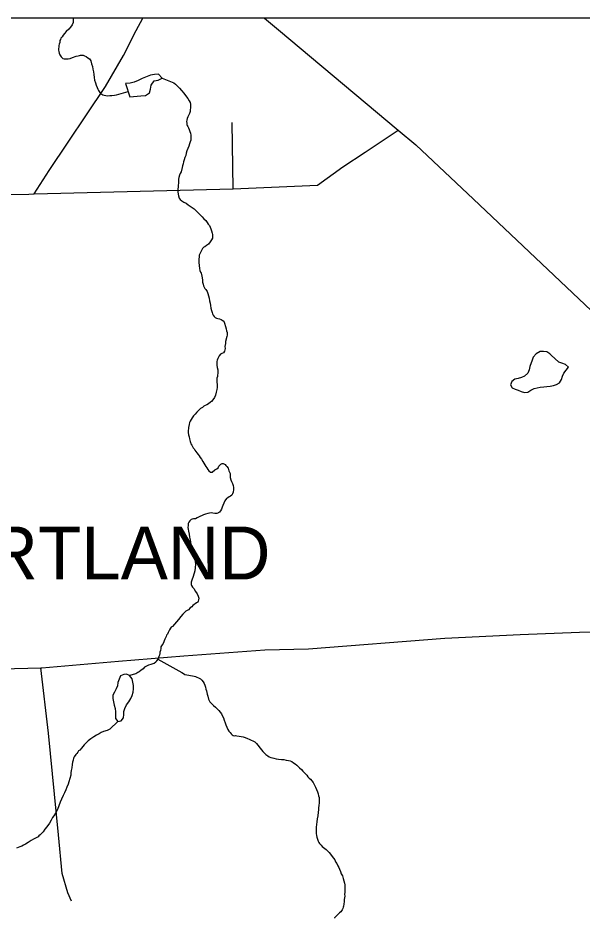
# Model space of a CAD drawing. Extents: x 103424 to 290657, y 38711 to 110967.
# Drawn here: x 109123 to 114482, y 102413 to 110967 of the extents above; entities that cross this region are included whole.
import ezdxf

# ---------------------------------------------------------------- set-up
doc = ezdxf.new("R2010")
doc.units = 0
for name, color, linetype in [('GM_X_City_Street', 7, 'Continuous'), ('GM_X_Corporation', 7, 'Continuous'), ('GM_X_Corporation_Text', 7, 'Continuous'), ('GM_X_County_Road', 7, 'Continuous'), ('GM_X_Minor_Lake', 7, 'Continuous'), ('GM_X_Minor_River', 7, 'Continuous')]:
    doc.layers.add(name, color=color, linetype=linetype)

msp = doc.modelspace()

# ---------------------------------------------------------------- linework, layer by layer
at = {"layer": 'GM_X_City_Street'}
msp.add_line((111163.5, 109345.6), (111153.7, 109973.9), dxfattribs=at)
for points in [[(109276.9, 109296.7), (111163.5, 109345.6), (111963.6, 109379.5), (112203.8, 109555.2), (112414.2, 109693.5), (112729.3, 109903)], [(104950.4, 104745), (108964.7, 104788.8), (109340, 104798.5), (109349.3, 104798.7), (110075.2, 104860), (110696.8, 104911.3), (111463.6, 104967.8), (111877.2, 104979.7), (113170.7, 105079.9), (113887, 105114.4), (114447.9, 105137.7), (115726.2, 105164.6)], [(109629.6, 102581.7), (109595.7, 102662.7), (109542, 102846.8), (109505.3, 103212.7), (109410.6, 104176.7), (109340, 104798.5)]]:
    msp.add_lwpolyline(points, dxfattribs=at)
at = {"layer": 'GM_X_Corporation'}
for points in [[(119699, 110967.2), (103423.7, 110967.2), (103423.7, 96534.8), (105081.7, 96574.5), (115542.1, 96665), (117026.4, 96688.2), (119663.9, 96690), (119706.4, 99064.2), (119709.7, 99445.7), (119720.8, 106006.3), (119719.8, 106322.8), (119716.9, 106542.5)], [(119675.5, 110967.2), (103423.7, 110967.2), (103423.7, 96476), (115542.1, 96665), (117026.4, 96688.2), (119663.9, 96690), (119681.7, 104183.1)], [(119699, 110967.2), (103423.7, 110967.2), (103423.7, 96534.8), (105081.7, 96574.5), (115542.1, 96665), (117026.4, 96688.2), (119663.9, 96690), (119706.4, 99064.2), (119709.7, 99445.7), (119720.8, 106006.3), (119719.8, 106322.8), (119716.9, 106542.5)]]:
    msp.add_lwpolyline(points, close=True, dxfattribs=at)
at = {"layer": 'GM_X_County_Road'}
for points in [[(109224.4, 109296.1), (109276.9, 109296.7), (109417.9, 109520.3), (109953.3, 110318.4), (110122.9, 110611.3), (110242.6, 110848.4), (110304.9, 110967.2)], [(111460.3, 110967.2), (111593.9, 110854.4), (112729.3, 109903), (112896.9, 109761.7), (113441.7, 109247.9), (114736.9, 108024.1), (115658.3, 107154.3), (115863.9, 106947.2), (116037.8, 106787.5), (116320.7, 106518.6)], [(104647.8, 109085.2), (105525.2, 109102.3), (105615.6, 109103.2), (105627.4, 109113.8), (105659.7, 109143.4), (105802.7, 109276.8), (106245.4, 109275.2), (107068.4, 109272.7), (107334.8, 109274.3), (109224.4, 109296.1)]]:
    msp.add_lwpolyline(points, dxfattribs=at)
at = {"layer": 'GM_X_Minor_Lake'}
msp.add_line((110143.6, 110346), (110183.6, 110217.8), dxfattribs=at)
for points in [[(110490.6, 110396.5), (110456.1, 110434.6), (110417.9, 110432.4), (110377.7, 110424.1), (110301.3, 110394.3)], [(110301.3, 110394.3), (110299.4, 110393.4), (110263.3, 110373.1), (110225.2, 110358.7), (110185, 110348.5), (110143.6, 110346)], [(110183.6, 110217.8), (110252.1, 110225.8), (110288.3, 110228), (110330.5, 110230.3), (110368.6, 110256.7), (110380.5, 110293), (110384.3, 110329.4), (110414.3, 110369.8), (110450.4, 110376.1), (110490.6, 110396.5)], [(114076.7, 107800.6), (114038.8, 107780.2), (114010.8, 107747.8), (113998.9, 107719.5), (113979.1, 107659), (113971.3, 107626.7), (113959.4, 107596.4), (113927.3, 107566), (113899.2, 107553.7), (113867.1, 107545.5), (113834.9, 107539.3), (113806.9, 107516.9), (113795, 107484.6), (113809.2, 107456.5), (113837.5, 107442.5), (113867.7, 107432.6), (113896, 107420.6), (113926.2, 107410.7), (113958.4, 107414.9)], [(114180.6, 107764.9), (114167.6, 107778.9), (114139.3, 107796.9), (114107.1, 107800.7), (114076.7, 107800.6)], [(113958.4, 107414.9), (113986.5, 107433.2), (114018.6, 107449.5), (114074.8, 107461.9), (114109, 107466.1), (114139.2, 107468.3), (114171.3, 107470.5), (114203.5, 107478.7), (114231.6, 107486.9), (114259.7, 107505.2), (114279.6, 107535.5), (114287.5, 107565.8), (114299.4, 107594.1), (114321.4, 107622.4), (114345.4, 107650.8), (114315, 107678.8), (114280.8, 107690.8), (114252.5, 107700.7), (114180.6, 107764.9)], [(110127.1, 104735.9), (110094.3, 104721.3), (110080.4, 104689), (110070.5, 104658.7), (110064.7, 104626.4), (110052.7, 104598.1), (110036.8, 104565.8), (110022.9, 104537.5), (110023.1, 104505.2), (110029.3, 104475), (110033.5, 104444.8), (110043.7, 104412.6), (110048, 104380.3), (110046.1, 104348.1), (110046.3, 104315.8)], [(110046.3, 104315.8), (110068.6, 104287.7), (110100.8, 104293.9), (110122.7, 104324.3), (110126.6, 104354.6), (110126.4, 104384.8), (110136.3, 104413.1), (110152.2, 104445.4), (110174.2, 104473.7), (110192.1, 104506.1), (110204, 104534.4), (110213.9, 104566.7), (110217.8, 104597), (110217.6, 104629.2), (110205.1, 104693.7), (110180.8, 104725.8), (110152.6, 104737.7), (110127.1, 104735.9)]]:
    msp.add_lwpolyline(points, dxfattribs=at)
at = {"layer": 'GM_X_Minor_River'}
for points in [[(109645.5, 110967.2), (109644.5, 110924), (109634.7, 110901.6)], [(109634.7, 110901.6), (109618.9, 110881.2), (109603.1, 110862.8), (109579.2, 110838.2), (109563.4, 110819.8), (109549.5, 110805.4), (109539.7, 110789.1), (109529.8, 110776.9), (109523.9, 110764.6), (109520.1, 110752.5), (109518.3, 110736.3), (109512.6, 110720), (109508.7, 110705.8), (109509, 110693.7), (109507.3, 110673.5), (109507.5, 110661.4), (109509.7, 110649.3), (109512, 110633.1), (109520.3, 110617.1), (109532.7, 110597.1), (109549.1, 110583.2), (109561.3, 110579.3), (109577.4, 110579.6), (109597.6, 110579.9), (109617.7, 110584.2), (109639.8, 110592.6), (109673.9, 110605.2), (109692, 110609.5), (109706.1, 110611.8), (109716.2, 110613.9), (109726.2, 110614.1), (109740.4, 110614.3), (109754.6, 110608.4), (109768.9, 110600.6), (109785.2, 110590.7), (109799.5, 110578.8), (109811.9, 110560.8), (109820.5, 110532.6), (109829, 110506.5), (109833.4, 110480.3), (109837.9, 110456.1), (109840.3, 110429.9), (109844.8, 110401.7), (109849.2, 110377.5), (109857.8, 110351.3), (109864.2, 110329.2), (109872.6, 110309.1), (109878.9, 110293), (109887.2, 110279), (109905.8, 110251), (109916.1, 110243.1), (109928.3, 110237.2), (109940.4, 110233.3), (109956.6, 110231.6), (109974.8, 110227.8), (109993, 110230.1), (110013.1, 110232.4), (110037.3, 110234.8), (110055.4, 110237.1), (110166.6, 110269.4)], [(110490.6, 110396.5), (110600.6, 110352.1), (110617, 110338.2), (110635.5, 110320.3), (110654, 110300.4), (110674.5, 110278.5), (110695.1, 110254.5), (110711.6, 110230.5), (110734.3, 110202.6), (110746.7, 110182.5), (110755.1, 110166.5), (110757.4, 110148.4), (110759.7, 110132.2), (110757.9, 110114), (110756.2, 110095.8), (110754.5, 110079.6), (110748.7, 110061.4), (110742.9, 110049.1), (110733.1, 110028.8), (110727.3, 110014.6), (110723.5, 109998.3), (110721.7, 109984.2), (110724, 109968), (110724.2, 109955.9), (110728.4, 109945.9), (110732.6, 109935.8), (110740.9, 109923.9), (110747.2, 109907.8), (110753.6, 109889.7), (110757.9, 109873.6), (110762.2, 109855.5), (110762.4, 109843.4), (110762.6, 109831.2), (110762.7, 109821.1), (110761, 109807), (110755.2, 109790.7), (110749.4, 109772.4), (110741.7, 109750.1), (110732, 109729.8), (110724.3, 109705.4), (110718.6, 109685.1), (110712.9, 109660.8), (110705.1, 109642.5), (110699.4, 109622.2), (110693.7, 109601.9), (110689.9, 109583.7), (110684.2, 109565.4), (110680.4, 109549.2), (110669, 109506.6), (110661.2, 109490.3), (110653.3, 109476.1), (110647.7, 109453.8), (110645.9, 109437.6), (110644.2, 109421.4), (110644.4, 109407.2), (110644.6, 109395.1), (110642.8, 109383), (110640.9, 109370.8), (110641.1, 109360.7), (110639.3, 109346.5), (110637.6, 109330.4), (110637.8, 109318.2), (110640.2, 109296), (110644.5, 109277.9), (110650.9, 109257.8), (110661.2, 109243.8), (110675.5, 109231.9), (110693.9, 109220.1), (110716.3, 109208.3), (110736.7, 109194.4), (110755.1, 109180.6), (110775.5, 109168.7), (110791.9, 109154.8), (110808.3, 109138.9), (110830.8, 109117), (110851.3, 109099.1), (110869.8, 109081.2), (110886.3, 109061.2), (110902.7, 109043.3), (110917.1, 109027.4), (110927.4, 109011.3), (110937.8, 108997.3), (110946.1, 108981.3), (110952.4, 108965.2), (110958.8, 108947.1), (110965.2, 108925), (110967.5, 108910.9), (110967.6, 108898.8), (110967.8, 108888.7), (110966, 108878.6), (110958.2, 108862.3), (110946.4, 108841.9), (110928.5, 108821.4), (110910.6, 108807), (110894.7, 108794.7), (110884.6, 108790.5), (110872.7, 108778.2)], [(110872.7, 108778.2), (110847.3, 108729.3), (110841.4, 108717.1), (110839.7, 108698.9), (110838.1, 108676.7), (110838.6, 108646.4), (110841.1, 108616.1), (110845.6, 108587.9), (110847.9, 108569.7), (110852.2, 108553.6), (110858.4, 108543.6), (110862.6, 108531.6), (110864.9, 108517.5), (110869.2, 108499.3), (110871.6, 108479.2), (110873.9, 108459), (110878.3, 108440.9), (110882.6, 108424.8), (110888.8, 108410.7), (110895.1, 108398.7), (110903.3, 108388.7), (110915.7, 108370.7), (110922.1, 108352.6), (110930.5, 108330.5), (110935, 108306.3), (110939.4, 108282.2), (110943.8, 108260), (110948.2, 108237.8), (110952.7, 108213.6), (110957, 108191.5), (110963.4, 108171.4), (110967.7, 108157.3), (110974, 108145.3), (110982.2, 108133.3), (110992.5, 108123.3), (111004.7, 108117.4), (111018.9, 108113.6), (111035.1, 108109.8), (111049.3, 108103.9), (111059.5, 108100.1), (111073.8, 108088.1), (111080.2, 108070), (111090.8, 108037.9), (111097.2, 108017.8), (111101.5, 107997.6), (111105.8, 107981.5), (111106.1, 107967.4), (111106.3, 107955.3), (111104.5, 107943.1), (111091.1, 107896.4), (111089.4, 107876.2), (111085.8, 107847.9), (111086.1, 107829.7), (111084.3, 107817.5), (111082.5, 107805.4), (111070.7, 107787), (111054.6, 107780.8), (111042.6, 107776.5), (111030.7, 107760.2), (111024.9, 107748), (111019.1, 107733.8), (111011.3, 107717.5), (111009.4, 107707.3), (111009.6, 107697.3), (111009.7, 107687.2), (111010, 107671), (111012.4, 107648.8), (111016.8, 107626.6), (111017.1, 107604.4), (111017.4, 107592.3), (111015.6, 107578.1), (111013.8, 107564), (111010, 107547.7), (111008.2, 107535.6), (111008.4, 107521.5), (111008.6, 107507.3), (111010.9, 107491.2), (111011.2, 107475), (111011.5, 107458.9), (111007.7, 107440.6), (111002.1, 107414.3), (110994.5, 107387.9), (110984.8, 107363.5), (110971, 107341.1), (110957.1, 107326.7), (110947.1, 107318.5), (110929.2, 107304.1), (110913.2, 107295.8), (110899.2, 107289.5), (110885.2, 107281.2), (110871.3, 107268.9), (110853.3, 107258.5), (110817.5, 107225.7), (110803.6, 107207.3), (110787.8, 107188.9), (110773.9, 107172.5), (110764.1, 107156.2), (110756.3, 107140), (110750.5, 107125.7), (110746.7, 107107.5), (110741.1, 107081.1)], [(110741.1, 107081.1), (110739.2, 107071), (110737.6, 107050.8), (110737.9, 107030.6), (110740.2, 107010.4), (110744.6, 106990.3), (110748.9, 106972.1), (110751.2, 106958), (110755.4, 106948), (110757.6, 106937.9), (110761.8, 106925.9), (110770.1, 106911.8), (110776.4, 106899.8), (110784.6, 106887.8), (110792.9, 106877.8), (110801.2, 106865.8), (110809.5, 106851.8), (110817.8, 106837.8), (110830.1, 106823.8), (110840.4, 106809.8), (110850.8, 106795.8), (110863.1, 106779.9), (110875.6, 106757.8), (110886, 106739.8), (110894.3, 106725.8), (110902.6, 106709.7), (110915, 106695.8), (110923.3, 106681.7), (110933.6, 106667.7), (110947.9, 106655.8), (110964.1, 106654), (110990, 106676.6), (111008, 106687), (111019.9, 106697.3), (111027.8, 106711.6), (111035.7, 106721.8), (111047.6, 106732), (111059.6, 106738.3), (111069.7, 106738.4), (111086, 106728.6), (111094.3, 106718.6), (111102.5, 106708.6), (111116.9, 106692.6), (111123.4, 106668.5), (111133.8, 106644.4), (111136.2, 106626.3), (111136.4, 106614.1), (111136.5, 106604), (111140.9, 106583.9), (111147.2, 106567.8), (111155.6, 106547.7), (111162, 106527.6), (111166.3, 106509.5), (111166.6, 106491.3), (111163, 106465), (111157.2, 106448.8), (111149.3, 106438.5), (111137.4, 106426.2), (111125.4, 106420), (111111.4, 106411.7), (111099.4, 106405.5), (111083.6, 106383), (111075.9, 106362.7), (111066.2, 106338.3), (111058.4, 106322), (111052.6, 106303.8), (111044.8, 106287.5), (111034.9, 106277.3), (111022.9, 106269), (111008.9, 106262.7), (110988.7, 106262.4), (110970.5, 106266.2), (110954.3, 106268), (110938.2, 106265.7), (110922.1, 106263.5), (110900, 106257.1), (110881.9, 106250.8), (110833.8, 106227.8), (110821.8, 106221.6), (110805.8, 106213.3), (110787.7, 106211), (110775.6, 106210.8), (110763.5, 106206.6), (110751.6, 106192.3), (110741.7, 106182.1), (110737.9, 106167.8), (110736.2, 106147.6), (110734.5, 106129.4), (110736.8, 106113.3), (110739.1, 106095.1), (110745.6, 106066.9), (110750.1, 106038.7), (110754.6, 106014.5), (110759, 105990.4), (110761.4, 105970.2), (110761.6, 105954), (110761.8, 105943.9), (110764, 105933.9), (110768.2, 105919.8), (110778.7, 105895.7), (110789.2, 105869.6)], [(110789.2, 105869.6), (110797.8, 105841.4), (110802.2, 105815.2), (110804.9, 105778.9), (110799.8, 105718.2), (110784.6, 105663.4), (110771, 105628.9), (110765.2, 105612.6), (110763.5, 105590.4), (110767.8, 105578.3), (110776.1, 105564.3), (110790.4, 105550.4), (110807.1, 105522.3), (110821.5, 105500.3), (110832, 105478.2), (110836.4, 105458.1), (110834.6, 105441.9), (110830.7, 105431.7), (110828.9, 105421.6), (110816.9, 105413.4), (110781, 105390.6), (110771.1, 105378.3), (110755.1, 105368), (110739.3, 105347.6), (110715.3, 105335.1), (110699.3, 105320.7), (110685.4, 105306.4), (110667.6, 105285.9), (110645.9, 105257.3), (110608.3, 105212.3), (110586.4, 105191.8), (110574.4, 105185.5), (110570.5, 105175.4), (110560.7, 105159.1), (110552.8, 105146.8), (110547, 105132.6), (110539.1, 105118.3), (110531.2, 105108.1), (110527.4, 105095.9), (110521.5, 105083.7), (110515.7, 105071.5), (110500.2, 105028.9), (110488.3, 105016.6), (110478.6, 104996.2), (110476.8, 104980), (110473, 104963.8), (110469.3, 104947.6), (110467.5, 104933.4), (110463.7, 104919.2), (110457.9, 104905), (110454, 104894.8), (110448.2, 104878.6), (110436.3, 104864.3), (110428.5, 104852), (110412.5, 104839.7), (110400.5, 104835.5), (110382.4, 104829.1), (110360.3, 104822.8), (110340.2, 104814.4), (110322.2, 104804), (110308.4, 104789.7), (110286.5, 104771.2), (110270.5, 104758.8), (110258.5, 104754.6), (110240.5, 104742.2), (110238.5, 104740.2), (110180.8, 104725.8)], [(110448.2, 104878.6), (110676.4, 104752.6), (110690.7, 104742.7), (110704.9, 104734.9), (110723.1, 104731.1), (110777.8, 104721.8), (110792, 104717.9), (110806.2, 104716.1), (110818.4, 104710.2), (110834.6, 104702.4), (110853, 104692.6), (110865.3, 104680.6), (110877.7, 104664.6), (110888, 104648.6), (110894.3, 104632.6), (110900.7, 104614.5), (110905, 104596.3), (110909.4, 104578.2), (110913.7, 104562.1), (110917.9, 104548), (110922.3, 104529.9), (110930.8, 104501.8), (110943.3, 104475.7), (110959.8, 104455.7), (110976.2, 104441.8), (110994.6, 104425.9), (111011, 104410), (111027.4, 104394.1), (111039.8, 104378.1), (111052.2, 104360.1), (111060.6, 104344), (111071, 104322), (111079.5, 104299.9), (111087.9, 104275.7), (111094.3, 104255.6), (111102.8, 104233.5), (111113.2, 104213.5), (111123.5, 104197.5), (111133.9, 104183.5), (111144.1, 104171.5), (111154.4, 104161.5), (111164.6, 104155.6), (111174.7, 104153.7), (111184.8, 104153.9), (111199, 104152.1), (111221.2, 104150.4), (111239.4, 104146.6), (111259.7, 104142.9), (111278, 104135), (111298.3, 104127.3), (111316.6, 104119.5), (111334.9, 104111.6), (111349.1, 104103.8), (111367.5, 104093.9), (111385.9, 104080.1), (111433.3, 104020.1), (111445.7, 104004.2), (111460.1, 103986.2), (111474.4, 103974.3), (111490.8, 103962.4), (111505, 103952.5), (111521.3, 103946.7), (111535.5, 103942.8), (111549.7, 103939), (111570, 103933.2), (111594.2, 103929.5), (111620.5, 103927.9), (111644.8, 103926.2), (111667, 103922.5), (111687.3, 103918.8), (111703.5, 103915), (111719.8, 103907.1), (111736.1, 103897.3), (111750.4, 103885.4), (111766.8, 103873.5), (111781.1, 103861.5), (111793.4, 103847.6), (111811.8, 103831.7), (111824.2, 103817.7), (111836.5, 103803.8), (111848.8, 103791.8), (111861.2, 103777.9), (111871.5, 103763.9), (111883.8, 103751.9), (111898.1, 103740), (111910.5, 103726), (111922.9, 103708), (111933.3, 103690), (111943.8, 103665.9), (111954.2, 103643.8), (111962.7, 103621.7), (111969, 103601.6), (111973.4, 103583.5), (111977.7, 103565.4), (111978.1, 103543.2), (111978.5, 103514.9), (111974.9, 103490.6)], [(110068.6, 104287.7), (109992.8, 104215.3), (109968.8, 104202.8), (109932.6, 104192.2), (109912.5, 104183.8), (109892.6, 104171.4), (109868.5, 104158.9), (109842.6, 104142.3), (109814.6, 104123.7), (109788.7, 104103.2), (109768.8, 104086.7), (109750.9, 104068.3), (109737.1, 104051.9), (109725.2, 104035.6), (109707.4, 104017.1), (109697.4, 104008.9), (109689.5, 103998.7), (109679.6, 103984.4), (109669.7, 103974.1), (109655.9, 103953.7), (109650.1, 103941.5), (109646.4, 103921.3), (109640.6, 103901), (109637, 103878.7), (109631.4, 103848.3), (109627.8, 103824), (109624.1, 103799.7), (109622.4, 103779.5), (109605.3, 103716.6), (109597.6, 103694.2), (109585.9, 103665.8), (109576.3, 103639.4), (109564.6, 103610.9), (109550.9, 103584.5), (109535.4, 103549.9), (109521.7, 103521.4), (109510.1, 103488.9), (109496.6, 103452.3), (109479, 103417.7), (109463.2, 103393.2), (109449.4, 103376.9), (109437.7, 103352.5), (109420, 103321.9), (109396.3, 103289.2), (109376.5, 103266.7), (109360.8, 103240.2), (109342.9, 103221.8), (109331, 103211.5), (109321, 103203.2), (109313.1, 103193), (109293.1, 103182.6), (109269, 103172.2), (109247.1, 103157.7), (109219.1, 103141.1), (109193.1, 103124.6), (109173.1, 103114.2), (109157.1, 103105.9), (109139.1, 103097.5), (109123, 103093.3), (109106.9, 103087)], [(111974.9, 103490.6), (111973.3, 103468.3), (111971.6, 103448.1), (111969.9, 103427.9), (111966.4, 103393.5), (111960.8, 103365.1), (111957.2, 103336.8), (111953.6, 103310.4), (111950, 103286.1), (111951, 103225.5), (111953.3, 103207.4), (111957.7, 103189.3), (111962, 103171.1), (111968.3, 103153.1), (111976.6, 103141), (111982.9, 103129), (111997.2, 103113.1), (112007.5, 103103.1), (112019.8, 103093.2), (112032.1, 103083.3), (112044.3, 103073.3), (112058.7, 103061.4), (112073, 103045.5), (112085.5, 103027.5), (112104, 103005.5), (112114.3, 102991.5), (112126.7, 102975.5), (112135.1, 102957.5), (112145.4, 102939.4), (112155.9, 102919.4), (112164.2, 102903.3), (112172.5, 102887.3), (112181, 102865.2), (112189.4, 102843.1), (112199.8, 102823), (112206.3, 102796.9), (112212.8, 102774.7), (112219.1, 102754.6), (112221.4, 102736.5), (112221.8, 102716.3), (112222.2, 102688), (112222.6, 102665.8), (112220.9, 102647.5), (112221.2, 102631.4), (112219.4, 102615.2), (112217.7, 102599), (112215.9, 102580.8), (112212.3, 102554.5), (112210.6, 102536.3), (112206.8, 102524.1), (112202.9, 102511.9), (112197.1, 102499.7), (112183.2, 102481.3), (112173.3, 102471.1), (112161.4, 102460.8), (112151.5, 102450.6), (112141.5, 102440.3), (112125.7, 102423.9), (112125.7, 102423.9), (112125.7, 102419.9)]]:
    msp.add_lwpolyline(points, dxfattribs=at)

# ---------------------------------------------------------------- texts
at = {"layer": 'GM_X_Corporation_Text'}
msp.add_text('KIRTLAND', height=503.12, rotation=0.00001, dxfattribs=at).set_placement((108189.7, 105636.5))

doc.saveas('drawing.dxf')
